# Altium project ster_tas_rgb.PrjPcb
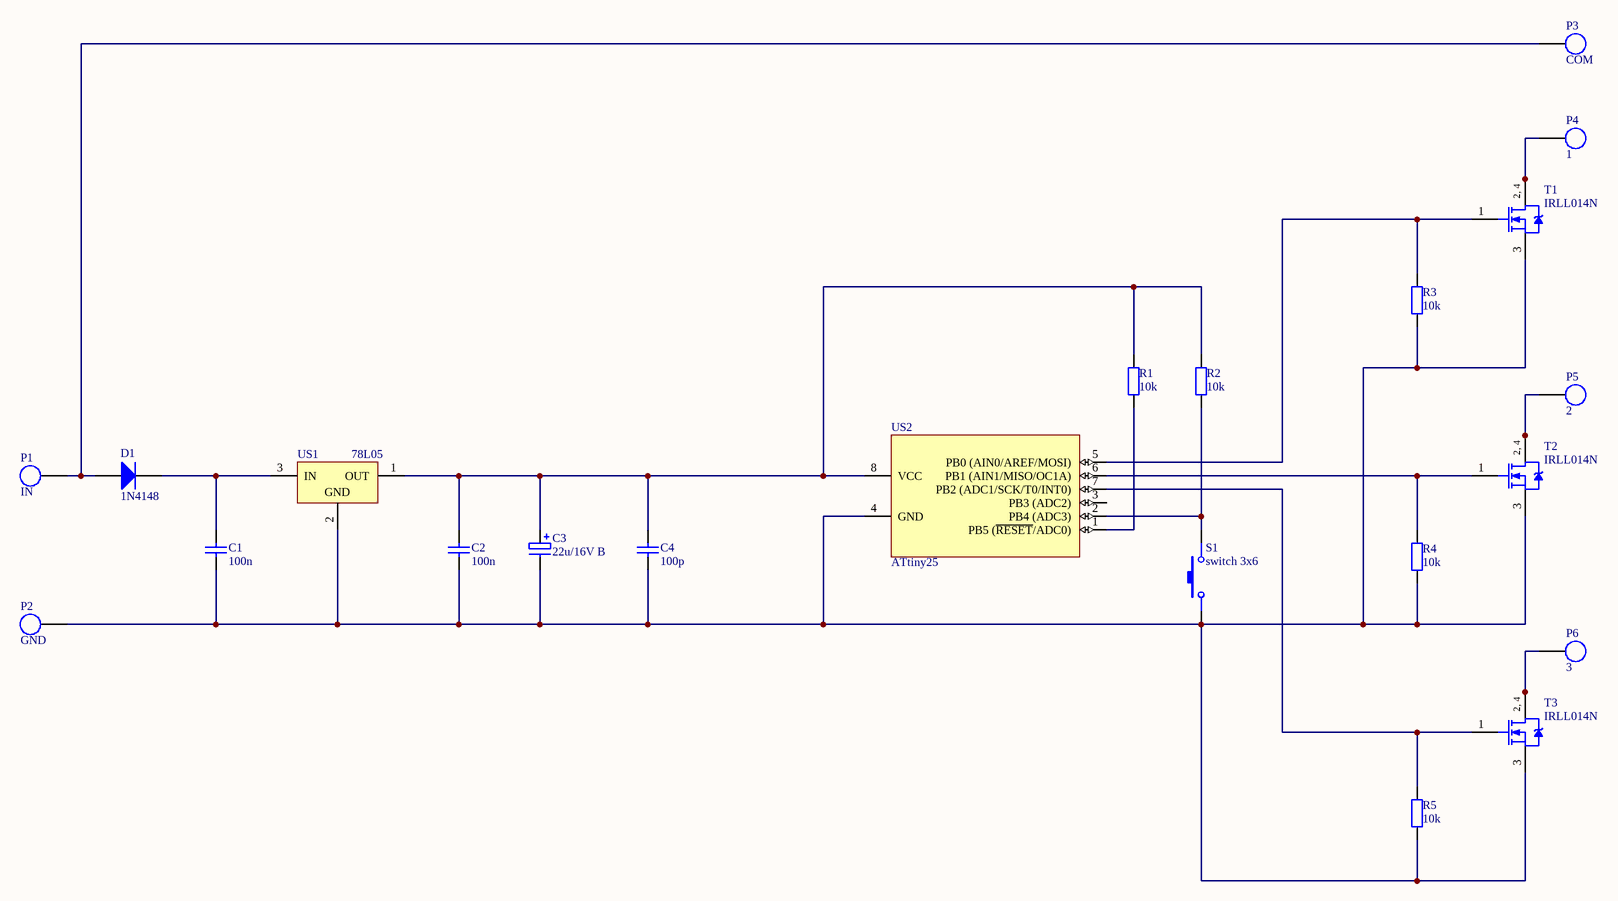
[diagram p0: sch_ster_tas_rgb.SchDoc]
1 sheet, 22 parts. Net scope: global (net labels, ports and power ports of the same name join across sheets).
Board file: pcb_ster_tas_rgb.PcbDoc

## Sheet sch_ster_tas_rgb.SchDoc
size A3

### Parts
C1  100n  [MELF-0805]
C2  100n  [MELF-0805]
C3  22u/16V B  [Tantal B 3528-1411]
C4  100p  [MELF-0805]
D1  1N4148  [dioda MINIMELF]
P1  IN  [Pad SMD 2x4mm]
P2  GND  [Pad SMD 2x4mm]
P3  COM  [Pad SMD 2x4mm]
P4  1  [Pad SMD 2x4mm]
P5  2  [Pad SMD 2x4mm]
P6  3  [Pad SMD 2x4mm]
R1  10k  [MELF-0805]
R2  10k  [MELF-0805]
R3  10k  [MELF-0805]
R4  10k  [MELF-0805]
R5  10k  [MELF-0805]
S1  switch 3x6  [tact switch 3x6]
T1  IRLL014N  [SOT-223]
T2  IRLL014N  [SOT-223]
T3  IRLL014N  [SOT-223]
US1  78L05  [PK03]
US2  ATtiny25  [8S2_N]

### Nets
NetC1_1: C1.1 C2.1 C3.2 C4.1 P2.1 R3.1 R4.1 R5.1 S1.1 T1.3(S) T2.3(S) T3.3(S) US1.2(GND) US2.4(GND)
NetC1_2: C1.2 D1.2(K) US1.3(IN)
NetC2_2: C2.2 C3.1 C4.2 R1.2 R2.2 US1.1(OUT) US2.8(VCC)
NetD1_1: D1.1(A) P1.1 P3.1
NetP4_1: P4.1 T1.2(D) T1.4(D)
NetP5_1: P5.1 T2.2(D) T2.4(D)
NetP6_1: P6.1 T3.2(D) T3.4(D)
NetR1_1: R1.1 US2.1(PB5_(~{RESET}/ADC0))
NetR2_1: R2.1 S1.2 US2.2(PB4_(ADC3))
NetR3_2: R3.2 T1.1(G) US2.5(PB0_(AIN0/AREF/MOSI))
NetR4_2: R4.2 T2.1(G) US2.6(PB1_(AIN1/MISO/OC1A))
NetR5_2: R5.2 T3.1(G) US2.7(PB2_(ADC1/SCK/T0/INT0))

Not connected (* = marked no-connect by the designer): US2 3(PB3_(ADC2))

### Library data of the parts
C1 C2 C4 = kondensator
C3 = kond biegunowy: Polarized Capacitor
D1 = Diode: Default Diode
P1-P6 = Pad
R1-R5 = rezystor
S1 = switch pojed
T1-T3 = IRLL014N: HEXFET Power MOSFET; Note: Pin 2 is electrically connected to pin 4.
US1 = µA78L05CPKR: Positive-Voltage Regulator; Note: Pin 2 is electrically connected to TAB.
US2 = ATtiny15L-1SC: 8-Bit AVR Microcontroller with 1K Byte of Flash Memory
